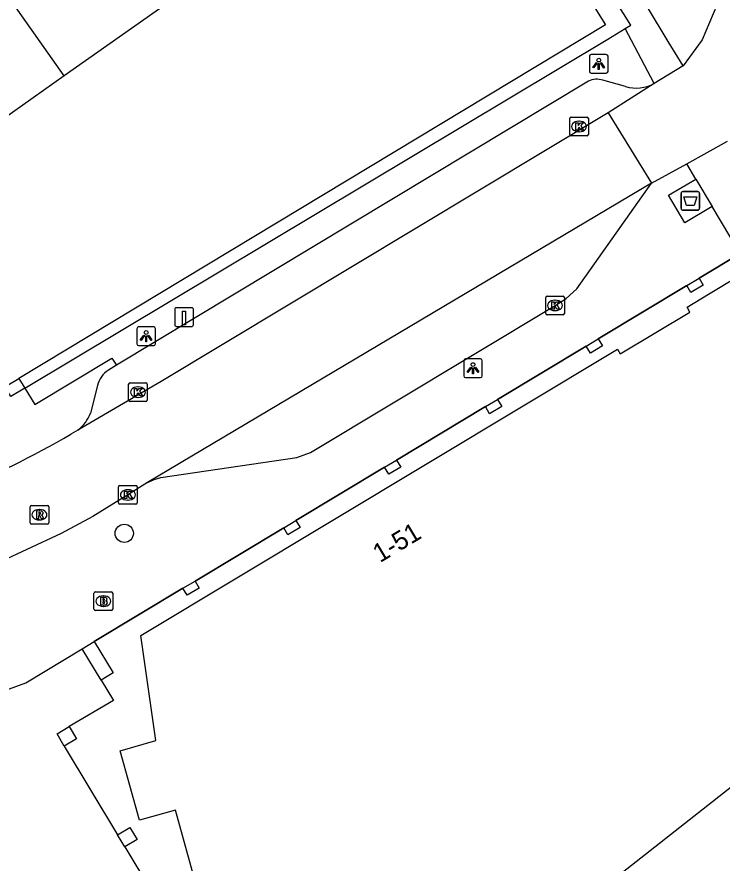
# Model space of a CAD drawing. Extents: x 159888 to 160757, y 384031 to 384746.
# Drawn here: x 160429.51 to 160467.29, y 384536.72 to 384582.04 of the extents above; entities that cross this region are included whole.
import ezdxf

# ---------------------------------------------------------------- set-up
doc = ezdxf.new("R2010")
doc.units = 0
for name, color, linetype in [('IMGEO_Afval_apart_plaats', 7, 'Continuous'), ('IMGEO_Boom', 7, 'Continuous'), ('IMGEO_Brandkraan', 7, 'Continuous'), ('IMGEO_Fietspad_gesloten', 7, 'Continuous'), ('IMGEO_Kolk', 7, 'Continuous'), ('IMGEO_Laadpaal', 7, 'Continuous'), ('IMGEO_Lichtpunt', 7, 'Continuous'), ('IMGEO_Pand', 7, 'Continuous'), ('IMGEO_Pand_nummerreeks', 7, 'Continuous'), ('IMGEO_Pand_overbouw', 7, 'Continuous'), ('IMGEO_Rijbaan_lokaal_gesloten', 7, 'Continuous'), ('IMGEO_Rijbaan_lokaal_open', 7, 'Continuous'), ('IMGEO_Rioolput', 7, 'Continuous'), ('IMGEO_Voetpad_gesloten', 7, 'Continuous'), ('IMGEO_Voetpad_open', 7, 'Continuous')]:
    doc.layers.add(name, color=color, linetype=linetype)

msp = doc.modelspace()

# ---------------------------------------------------------------- linework, layer by layer
at = {"layer": 'IMGEO_Afval_apart_plaats'}
for p, q in [((160465.088, 384571.791), (160465.088, 384572.591)), ((160465.088, 384572.591), (160465.088, 384571.791)), ((160465.188, 384572.691), (160465.978, 384572.691)), ((160465.978, 384572.691), (160465.188, 384572.691)), ((160466.078, 384572.591), (160466.078, 384571.791)), ((160466.078, 384571.791), (160466.078, 384572.591)), ((160465.978, 384571.691), (160465.188, 384571.691)), ((160465.188, 384571.691), (160465.978, 384571.691))]:
    msp.add_line(p, q, dxfattribs=at)
msp.add_lwpolyline([(160465.231, 384572.405), (160465.935, 384572.405), (160465.786, 384571.935), (160465.38, 384571.935), (160465.231, 384572.405)], dxfattribs=at)
for centre, start, end in [((160465.188, 384572.591), 90, 180), ((160465.188, 384572.591), 90, 180), ((160465.978, 384572.591), 0, 90), ((160465.978, 384572.591), 360, 90), ((160465.188, 384571.791), 180, 270), ((160465.188, 384571.791), 180, 270), ((160465.978, 384571.791), 270, 0), ((160465.978, 384571.791), 270, 0)]:
    msp.add_arc(centre, 0.1, start, end, dxfattribs=at)
at = {"layer": 'IMGEO_Boom'}
msp.add_circle((160435.258, 384554.38), 0.489, dxfattribs=at)
at = {"layer": 'IMGEO_Brandkraan'}
for p, q in [((160433.637, 384550.323), (160433.637, 384551.175)), ((160433.712, 384551.249), (160434.564, 384551.249)), ((160434.125, 384551.029), (160434.15, 384551.029)), ((160434.638, 384551.175), (160434.638, 384550.323)), ((160434.564, 384550.249), (160433.712, 384550.249)), ((160434.148, 384550.469), (160434.123, 384550.469))]:
    msp.add_line(p, q, dxfattribs=at)
for points in [[(160433.637, 384550.323), (160433.637, 384551.175)], [(160433.712, 384551.249), (160434.564, 384551.249)], [(160434.638, 384551.175), (160434.638, 384550.323)], [(160433.985, 384550.949), (160433.985, 384550.549), (160434.198, 384550.549)], [(160434.216, 384550.949), (160433.985, 384550.949)], [(160434.164, 384550.868), (160434.11, 384550.868), (160434.11, 384550.792)], [(160434.11, 384550.792), (160434.163, 384550.792)], [(160434.172, 384550.716), (160434.11, 384550.716), (160434.11, 384550.635)], [(160434.11, 384550.635), (160434.172, 384550.635)], [(160434.564, 384550.249), (160433.712, 384550.249)]]:
    msp.add_lwpolyline(points, dxfattribs=at)
for centre, radius, start, end in [((160433.714, 384551.173), 0.0765, 91.552, 178.448), ((160433.714, 384551.173), 0.0765, 91.552, 178.448), ((160434.562, 384551.173), 0.0765, 1.552, 88.448), ((160434.562, 384551.173), 0.0765, 1.552, 88.448), ((160434.165, 384550.83), 0.0379, 267.8285, 90.9355), ((160434.173, 384550.675), 0.0404, 269.8759, 90.5077), ((160434.204, 384550.8), 0.251, 268.6676, 293.5347), ((160434.22, 384550.804), 0.145, 59.4692, 91.5367), ((160434.245, 384550.851), 0.0922, 285.5137, 58.1501), ((160434.25, 384550.659), 0.105, 301.3115, 78.989), ((160433.714, 384550.325), 0.0765, 181.552, 268.448), ((160433.714, 384550.325), 0.0765, 181.552, 268.448), ((160434.562, 384550.325), 0.0765, 271.552, 358.448), ((160434.562, 384550.325), 0.0765, 271.552, 358.448)]:
    msp.add_arc(centre, radius, start, end, dxfattribs=at)
for centre, major_axis, ratio, start_param, end_param in [((160434.124, 384550.749), (-0.387, 0.002), 0.722429, 4.712389, 7.853982), ((160434.149, 384550.749), (-0.39, 0.002), 0.717154, 1.570796, 4.712389)]:
    msp.add_ellipse(centre, major_axis=major_axis, ratio=ratio, start_param=start_param, end_param=end_param, dxfattribs=at)
at = {"layer": 'IMGEO_Fietspad_gesloten'}
msp.add_lwpolyline([(160465.195, 384579.421), (160464.393, 384580.732), (160446.684, 384610.177)], dxfattribs=at)
at = {"layer": 'IMGEO_Kolk'}
for p, q in [((160459.123, 384575.749), (160459.123, 384576.601)), ((160459.198, 384576.675), (160460.05, 384576.675)), ((160459.611, 384576.455), (160459.636, 384576.455)), ((160460.124, 384576.601), (160460.124, 384575.749)), ((160459.634, 384575.895), (160459.609, 384575.895)), ((160460.05, 384575.675), (160459.198, 384575.675)), ((160457.837, 384566.163), (160457.837, 384567.015)), ((160457.912, 384567.089), (160458.764, 384567.089)), ((160458.325, 384566.869), (160458.35, 384566.869)), ((160458.838, 384567.015), (160458.838, 384566.163)), ((160458.764, 384566.089), (160457.912, 384566.089)), ((160458.348, 384566.309), (160458.323, 384566.309)), ((160435.491, 384561.517), (160435.491, 384562.369)), ((160435.566, 384562.443), (160436.418, 384562.443)), ((160436.492, 384562.369), (160436.492, 384561.517)), ((160435.979, 384562.223), (160436.004, 384562.223)), ((160436.418, 384561.443), (160435.566, 384561.443)), ((160436.002, 384561.663), (160435.977, 384561.663)), ((160434.951, 384556.014), (160434.951, 384556.866)), ((160435.026, 384556.94), (160435.878, 384556.94)), ((160435.952, 384556.866), (160435.952, 384556.014)), ((160435.439, 384556.72), (160435.464, 384556.72)), ((160435.462, 384556.16), (160435.437, 384556.16)), ((160435.878, 384555.94), (160435.026, 384555.94))]:
    msp.add_line(p, q, dxfattribs=at)
for points in [[(160459.123, 384575.749), (160459.123, 384576.601)], [(160459.198, 384576.675), (160460.05, 384576.675)], [(160459.444, 384576.375), (160459.567, 384576.375), (160459.567, 384576.224), (160459.697, 384576.375), (160459.861, 384576.375), (160459.715, 384576.224), (160459.868, 384575.975), (160459.716, 384575.975), (160459.631, 384576.139), (160459.567, 384576.072), (160459.567, 384575.975), (160459.444, 384575.975), (160459.444, 384576.375)], [(160460.124, 384576.601), (160460.124, 384575.749)], [(160460.05, 384575.675), (160459.198, 384575.675)], [(160457.837, 384566.163), (160457.837, 384567.015)], [(160457.912, 384567.089), (160458.764, 384567.089)], [(160458.838, 384567.015), (160458.838, 384566.163)], [(160458.158, 384566.789), (160458.281, 384566.789), (160458.281, 384566.638), (160458.411, 384566.789), (160458.575, 384566.789), (160458.429, 384566.638), (160458.582, 384566.389), (160458.43, 384566.389), (160458.345, 384566.553), (160458.281, 384566.486), (160458.281, 384566.389), (160458.158, 384566.389), (160458.158, 384566.789)], [(160458.764, 384566.089), (160457.912, 384566.089)], [(160435.491, 384561.517), (160435.491, 384562.369)], [(160435.566, 384562.443), (160436.418, 384562.443)], [(160436.492, 384562.369), (160436.492, 384561.517)], [(160435.812, 384562.143), (160435.935, 384562.143), (160435.935, 384561.992), (160436.065, 384562.143), (160436.229, 384562.143), (160436.083, 384561.992), (160436.236, 384561.743), (160436.084, 384561.743), (160435.999, 384561.907), (160435.935, 384561.84), (160435.935, 384561.743), (160435.812, 384561.743), (160435.812, 384562.143)], [(160436.418, 384561.443), (160435.566, 384561.443)], [(160434.951, 384556.014), (160434.951, 384556.866)], [(160435.026, 384556.94), (160435.878, 384556.94)], [(160435.952, 384556.866), (160435.952, 384556.014)], [(160435.272, 384556.64), (160435.395, 384556.64), (160435.395, 384556.489), (160435.525, 384556.64), (160435.689, 384556.64), (160435.543, 384556.489), (160435.696, 384556.24), (160435.544, 384556.24), (160435.459, 384556.404), (160435.395, 384556.337), (160435.395, 384556.24), (160435.272, 384556.24), (160435.272, 384556.64)], [(160435.878, 384555.94), (160435.026, 384555.94)]]:
    msp.add_lwpolyline(points, dxfattribs=at)
for centre, start, end in [((160459.2, 384576.599), 91.552, 178.448), ((160459.2, 384576.599), 91.552, 178.448), ((160460.048, 384576.599), 1.552, 88.448), ((160460.048, 384576.599), 1.552, 88.448), ((160459.2, 384575.751), 181.552, 268.448), ((160459.2, 384575.751), 181.552, 268.448), ((160460.048, 384575.751), 271.552, 358.448), ((160460.048, 384575.751), 271.552, 358.448), ((160457.914, 384567.013), 91.552, 178.448), ((160457.914, 384567.013), 91.552, 178.448), ((160458.762, 384567.013), 1.552, 88.448), ((160458.762, 384567.013), 1.552, 88.448), ((160457.914, 384566.165), 181.552, 268.448), ((160457.914, 384566.165), 181.552, 268.448), ((160458.762, 384566.165), 271.552, 358.448), ((160458.762, 384566.165), 271.552, 358.448), ((160435.568, 384562.367), 91.552, 178.448), ((160435.568, 384562.367), 91.552, 178.448), ((160436.416, 384562.367), 1.552, 88.448), ((160436.416, 384562.367), 1.552, 88.448), ((160435.568, 384561.519), 181.552, 268.448), ((160435.568, 384561.519), 181.552, 268.448), ((160436.416, 384561.519), 271.552, 358.448), ((160436.416, 384561.519), 271.552, 358.448), ((160435.028, 384556.864), 91.552, 178.448), ((160435.028, 384556.864), 91.552, 178.448), ((160435.876, 384556.864), 1.552, 88.448), ((160435.876, 384556.864), 1.552, 88.448), ((160435.028, 384556.016), 181.552, 268.448), ((160435.028, 384556.016), 181.552, 268.448), ((160435.876, 384556.016), 271.552, 358.448), ((160435.876, 384556.016), 271.552, 358.448)]:
    msp.add_arc(centre, 0.0765, start, end, dxfattribs=at)
for centre, major_axis, ratio, start_param, end_param in [((160459.61, 384576.175), (-0.387, 0.002), 0.722429, 4.712389, 7.853982), ((160459.635, 384576.175), (-0.39, 0.002), 0.717154, 1.570796, 4.712389), ((160458.324, 384566.589), (-0.387, 0.002), 0.722429, 4.712389, 7.853982), ((160458.349, 384566.589), (-0.39, 0.002), 0.717154, 1.570796, 4.712389), ((160435.978, 384561.943), (-0.387, 0.002), 0.722429, 4.712389, 7.853982), ((160436.003, 384561.943), (-0.39, 0.002), 0.717154, 1.570796, 4.712389), ((160435.438, 384556.44), (-0.387, 0.002), 0.722429, 4.712389, 7.853982), ((160435.463, 384556.44), (-0.39, 0.002), 0.717154, 1.570796, 4.712389)]:
    msp.add_ellipse(centre, major_axis=major_axis, ratio=ratio, start_param=start_param, end_param=end_param, dxfattribs=at)
at = {"layer": 'IMGEO_Laadpaal'}
for p, q in [((160437.963, 384566.384), (160437.963, 384565.543)), ((160437.963, 384566.384), (160437.963, 384565.543)), ((160438.879, 384566.468), (160438.038, 384566.468)), ((160438.879, 384566.468), (160438.038, 384566.468)), ((160438.963, 384565.552), (160438.963, 384566.393)), ((160438.963, 384565.552), (160438.963, 384566.393)), ((160438.047, 384565.468), (160438.888, 384565.468)), ((160438.047, 384565.468), (160438.888, 384565.468))]:
    msp.add_line(p, q, dxfattribs=at)
msp.add_lwpolyline([(160438.378, 384566.281), (160438.538, 384566.281), (160438.538, 384565.548), (160438.378, 384565.548), (160438.378, 384566.281)], dxfattribs=at)
for centre, start, end in [((160438.041, 384566.39), 92.4484, 184.2845), ((160438.041, 384566.39), 92.4484, 184.2845), ((160438.885, 384566.39), 2.4484, 94.2845), ((160438.885, 384566.39), 2.4484, 94.2845), ((160438.041, 384565.546), 182.4484, 274.2845), ((160438.041, 384565.546), 182.4484, 274.2845), ((160438.885, 384565.546), 272.4484, 4.2845), ((160438.885, 384565.546), 272.4484, 4.2845)]:
    msp.add_arc(centre, 0.0779, start, end, dxfattribs=at)
at = {"layer": 'IMGEO_Lichtpunt'}
for p, q in [((160461.082, 384580.029), (160460.274, 384580.029)), ((160461.082, 384580.029), (160460.274, 384580.029)), ((160460.18, 384579.934), (160460.18, 384579.127)), ((160460.18, 384579.934), (160460.18, 384579.127)), ((160461.176, 384579.127), (160461.176, 384579.934)), ((160461.176, 384579.127), (160461.176, 384579.934)), ((160460.274, 384579.033), (160461.082, 384579.033)), ((160460.274, 384579.033), (160461.082, 384579.033)), ((160435.932, 384565.341), (160435.932, 384564.534)), ((160435.932, 384565.341), (160435.932, 384564.534)), ((160436.834, 384565.436), (160436.026, 384565.436)), ((160436.834, 384565.436), (160436.026, 384565.436)), ((160436.928, 384564.534), (160436.928, 384565.341)), ((160436.928, 384564.534), (160436.928, 384565.341)), ((160436.026, 384564.44), (160436.834, 384564.44)), ((160436.026, 384564.44), (160436.834, 384564.44)), ((160454.345, 384563.72), (160453.537, 384563.72)), ((160454.345, 384563.72), (160453.537, 384563.72)), ((160453.443, 384563.625), (160453.443, 384562.818)), ((160453.443, 384563.625), (160453.443, 384562.818)), ((160454.439, 384562.818), (160454.439, 384563.625)), ((160454.439, 384562.818), (160454.439, 384563.625)), ((160453.537, 384562.724), (160454.345, 384562.724)), ((160453.537, 384562.724), (160454.345, 384562.724))]:
    msp.add_line(p, q, dxfattribs=at)
for points in [[(160460.554, 384579.598), (160460.593, 384579.57), (160460.405, 384579.308), (160460.367, 384579.335), (160460.554, 384579.598)], [(160460.656, 384579.55), (160460.703, 384579.55), (160460.703, 384579.228), (160460.656, 384579.228), (160460.656, 384579.55)], [(160460.766, 384579.57), (160460.804, 384579.597), (160460.991, 384579.335), (160460.952, 384579.307), (160460.766, 384579.57)], [(160436.306, 384565.005), (160436.345, 384564.977), (160436.157, 384564.715), (160436.119, 384564.742), (160436.306, 384565.005)], [(160436.408, 384564.957), (160436.455, 384564.957), (160436.455, 384564.635), (160436.408, 384564.635), (160436.408, 384564.957)], [(160436.518, 384564.977), (160436.556, 384565.004), (160436.743, 384564.742), (160436.704, 384564.714), (160436.518, 384564.977)], [(160453.817, 384563.289), (160453.856, 384563.261), (160453.668, 384562.999), (160453.63, 384563.026), (160453.817, 384563.289)], [(160453.919, 384563.241), (160453.966, 384563.241), (160453.966, 384562.919), (160453.919, 384562.919), (160453.919, 384563.241)], [(160454.029, 384563.261), (160454.067, 384563.288), (160454.254, 384563.026), (160454.215, 384562.998), (160454.029, 384563.261)]]:
    msp.add_lwpolyline(points, dxfattribs=at)
for centre in [(160460.679, 384579.732), (160436.431, 384565.139), (160453.942, 384563.423)]:
    msp.add_circle(centre, 0.0994, dxfattribs=at)
for centre, start, end in [((160460.274, 384579.934), 90, 180), ((160460.274, 384579.934), 90, 180), ((160461.082, 384579.934), 0, 90), ((160461.082, 384579.934), 0, 90), ((160460.274, 384579.127), 180, 270), ((160460.274, 384579.127), 180, 270), ((160461.082, 384579.127), 270, 0), ((160461.082, 384579.127), 270, 360), ((160436.026, 384565.341), 90, 180), ((160436.026, 384565.341), 90, 180), ((160436.834, 384565.341), 0, 90), ((160436.834, 384565.341), 0, 90), ((160436.026, 384564.534), 180, 270), ((160436.026, 384564.534), 180, 270), ((160436.834, 384564.534), 270, 0), ((160436.834, 384564.534), 270, 360), ((160453.537, 384563.625), 90, 180), ((160453.537, 384563.625), 90, 180), ((160454.345, 384563.625), 0, 90), ((160454.345, 384563.625), 0, 90), ((160453.537, 384562.818), 180, 270), ((160453.537, 384562.818), 180, 270), ((160454.345, 384562.818), 270, 0), ((160454.345, 384562.818), 270, 360)]:
    msp.add_arc(centre, 0.0946, start, end, dxfattribs=at)
at = {"layer": 'IMGEO_Pand'}
for points in [[(160453.478, 384593.674), (160461.033, 384581.623), (160429.614, 384562.681)], [(160432.047, 384578.89), (160429.131, 384583.037), (160435.204, 384587.306), (160438.111, 384583.181)], [(160438.111, 384583.181), (160432.047, 384578.89)], [(160432.047, 384578.89), (160423.166, 384572.604), (160426.417, 384566.77), (160428.859, 384562.226)], [(160445.899, 384523.596), (160445.557, 384524.165), (160445.433, 384524.372), (160443.403, 384527.748), (160439.447, 384534.325), (160438.003, 384539.546), (160436.076, 384539.012), (160435.044, 384542.736), (160436.954, 384543.281), (160436.151, 384548.915), (160461.68, 384564.249), (160461.834, 384563.992), (160465.563, 384566.236), (160465.409, 384566.493), (160466.566, 384567.188), (160468.137, 384568.133), (160468.762, 384567.092), (160478.909, 384550.185)], [(160465.394, 384567.655), (160466.054, 384568.046)], [(160466.054, 384568.046), (160466.278, 384567.667), (160465.618, 384567.276), (160465.394, 384567.655)], [(160460.003, 384564.411), (160460.651, 384564.801)], [(160460.651, 384564.801), (160460.877, 384564.424), (160460.229, 384564.034), (160460.003, 384564.411)], [(160428.859, 384562.226), (160429.614, 384562.681)], [(160454.605, 384561.168), (160455.253, 384561.557)], [(160455.253, 384561.557), (160455.479, 384561.18), (160454.832, 384560.791), (160454.605, 384561.168)], [(160449.201, 384557.92), (160449.85, 384558.308)], [(160449.85, 384558.308), (160450.076, 384557.93), (160449.426, 384557.542), (160449.201, 384557.92)], [(160443.8, 384554.678), (160444.449, 384555.066)], [(160444.449, 384555.066), (160444.675, 384554.688), (160444.026, 384554.3), (160443.8, 384554.678)], [(160438.4, 384551.441), (160439.051, 384551.824)], [(160439.051, 384551.824), (160439.274, 384551.445), (160438.623, 384551.062), (160438.4, 384551.441)], [(160479.161, 384549.765), (160471.203, 384543.477), (160445.899, 384523.596)], [(160433.002, 384548.194), (160433.645, 384548.583)], [(160433.645, 384548.583), (160434.663, 384546.901), (160434.02, 384546.512), (160433.002, 384548.194)], [(160431.658, 384543.639), (160432.312, 384544.026), (160432.7, 384543.369), (160432.045, 384542.983), (160431.658, 384543.639)], [(160434.9, 384538.236), (160435.551, 384538.628), (160435.942, 384537.979), (160435.29, 384537.588), (160434.9, 384538.236)]]:
    msp.add_lwpolyline(points, dxfattribs=at)
at = {"layer": 'IMGEO_Pand_overbouw'}
for points in [[(160468.257, 384569.373), (160466.054, 384568.046), (160466.278, 384567.667), (160465.618, 384567.276), (160465.394, 384567.655), (160460.651, 384564.801), (160460.877, 384564.424), (160460.229, 384564.034), (160460.003, 384564.411), (160455.253, 384561.557), (160455.479, 384561.18), (160454.832, 384560.791), (160454.605, 384561.168), (160449.85, 384558.308), (160450.076, 384557.93), (160449.426, 384557.542), (160449.201, 384557.92), (160444.449, 384555.066), (160444.675, 384554.688), (160444.026, 384554.3), (160443.8, 384554.678), (160439.051, 384551.824), (160439.274, 384551.445), (160438.623, 384551.062), (160438.4, 384551.441), (160433.645, 384548.583), (160434.663, 384546.901), (160434.02, 384546.512), (160434.677, 384545.426), (160432.312, 384544.026), (160432.7, 384543.369), (160432.045, 384542.983), (160434.9, 384538.236), (160435.551, 384538.628), (160435.942, 384537.979), (160435.29, 384537.588), (160438.144, 384532.838)], [(160439.447, 384534.325), (160438.003, 384539.546), (160436.076, 384539.012), (160435.044, 384542.736), (160436.954, 384543.281), (160436.151, 384548.915), (160461.68, 384564.249), (160461.834, 384563.992), (160465.563, 384566.236), (160465.409, 384566.493), (160466.566, 384567.188), (160468.137, 384568.133)]]:
    msp.add_lwpolyline(points, dxfattribs=at)
at = {"layer": 'IMGEO_Rijbaan_lokaal_gesloten'}
for points in [[(160467.002, 384582.668), (160466.21, 384580.825), (160465.195, 384579.421)], [(160465.195, 384579.421), (160463.642, 384578.473)], [(160463.642, 384578.473), (160461.191, 384576.901)], [(160461.191, 384576.901), (160463.506, 384573.139)], [(160465.391, 384574.168), (160467.569, 384575.383)], [(160463.506, 384573.139), (160465.391, 384574.168)]]:
    msp.add_lwpolyline(points, dxfattribs=at)
at = {"layer": 'IMGEO_Rijbaan_lokaal_open'}
for points in [[(160461.191, 384576.901), (160437.228, 384562.516), (160432.767, 384559.91)], [(160463.506, 384573.139), (160436.506, 384557.107)], [(160432.767, 384559.91), (160432.39, 384559.689)], [(160436.506, 384557.107), (160435.452, 384556.441), (160433.566, 384555.285), (160431.872, 384554.363), (160428.176, 384552.657), (160425.402, 384551.486)]]:
    msp.add_lwpolyline(points, dxfattribs=at)
msp.add_arc((160405.714, 384605.651), 53.143, 292.534, 300.1303, dxfattribs=at)
at = {"layer": 'IMGEO_Rioolput'}
for p, q in [((160430.215, 384554.952), (160430.215, 384555.804)), ((160430.29, 384555.878), (160431.142, 384555.878)), ((160430.703, 384555.658), (160430.728, 384555.658)), ((160431.216, 384555.804), (160431.216, 384554.952)), ((160430.726, 384555.098), (160430.701, 384555.098)), ((160431.142, 384554.878), (160430.29, 384554.878))]:
    msp.add_line(p, q, dxfattribs=at)
for points in [[(160430.215, 384554.952), (160430.215, 384555.804)], [(160430.29, 384555.878), (160431.142, 384555.878)], [(160430.804, 384555.576), (160430.552, 384555.578), (160430.552, 384555.178)], [(160430.73, 384555.497), (160430.676, 384555.497), (160430.676, 384555.416)], [(160431.216, 384555.804), (160431.216, 384554.952)], [(160430.552, 384555.178), (160430.676, 384555.178), (160430.676, 384555.34), (160430.687, 384555.34)], [(160430.676, 384555.416), (160430.728, 384555.416)], [(160430.734, 384555.311), (160430.805, 384555.178), (160430.945, 384555.178), (160430.88, 384555.304)], [(160431.142, 384554.878), (160430.29, 384554.878)]]:
    msp.add_lwpolyline(points, dxfattribs=at)
for centre, radius, start, end in [((160430.292, 384555.802), 0.0765, 91.552, 178.448), ((160430.292, 384555.802), 0.0765, 91.552, 178.448), ((160430.736, 384555.401), 0.0964, 77.0061, 93.1865), ((160430.75, 384555.458), 0.0378, 276.6634, 79.6772), ((160430.803, 384555.466), 0.109, 350.3612, 89.416), ((160431.14, 384555.802), 0.0765, 1.552, 88.448), ((160431.14, 384555.802), 0.0765, 1.552, 88.448), ((160430.686, 384555.287), 0.0533, 26.0293, 88.6989), ((160430.712, 384555.605), 0.19, 274.7715, 282.9687), ((160430.801, 384555.466), 0.112, 277.5842, 350.9817), ((160430.785, 384555.251), 0.108, 29.5134, 73.7905), ((160430.292, 384554.954), 0.0765, 181.552, 268.448), ((160430.292, 384554.954), 0.0765, 181.552, 268.448), ((160431.14, 384554.954), 0.0765, 271.552, 358.448), ((160431.14, 384554.954), 0.0765, 271.552, 358.448)]:
    msp.add_arc(centre, radius, start, end, dxfattribs=at)
for centre, major_axis, ratio, start_param, end_param in [((160430.702, 384555.378), (-0.387, 0.002), 0.722429, 4.712389, 7.853982), ((160430.727, 384555.378), (-0.39, 0.002), 0.717154, 1.570796, 4.712389)]:
    msp.add_ellipse(centre, major_axis=major_axis, ratio=ratio, start_param=start_param, end_param=end_param, dxfattribs=at)
at = {"layer": 'IMGEO_Voetpad_gesloten'}
for points in [[(160466.748, 384571.889), (160465.295, 384571.022), (160464.418, 384572.493), (160465.871, 384573.36)], [(160465.871, 384573.36), (160466.748, 384571.889)]]:
    msp.add_lwpolyline(points, dxfattribs=at)
at = {"layer": 'IMGEO_Voetpad_open'}
for points in [[(160462.088, 384581.42), (160462.394, 384581.605), (160458.462, 384587.864), (160454.434, 384594.24), (160453.478, 384593.674)], [(160429.927, 384562.164), (160461.157, 384580.856), (160462.088, 384581.42)], [(160463.642, 384578.473), (160462.088, 384581.42)], [(160460.123, 384578.61), (160434.834, 384563.381)], [(160462.118, 384578.314), (160460.898, 384578.651)], [(160465.871, 384573.36), (160465.391, 384574.168)], [(160436.506, 384557.107), (160436.857, 384557.271), (160437.223, 384557.371), (160444.495, 384558.444), (160445.235, 384558.712), (160458.337, 384566.59), (160458.925, 384566.958), (160459.498, 384567.481), (160463.506, 384573.139)], [(160468.257, 384569.373), (160466.748, 384571.889)], [(160466.054, 384568.046), (160468.257, 384569.373)], [(160460.651, 384564.801), (160465.394, 384567.655)], [(160455.253, 384561.557), (160460.003, 384564.411)], [(160429.927, 384562.164), (160430.463, 384561.279), (160434.587, 384563.77), (160434.834, 384563.381)], [(160434.834, 384563.381), (160434.412, 384563.116)], [(160429.614, 384562.681), (160429.927, 384562.164)], [(160433.831, 384562.3), (160433.45, 384560.821)], [(160429.927, 384562.164), (160429.173, 384561.715), (160428.859, 384562.226)], [(160449.85, 384558.308), (160454.605, 384561.168)], [(160444.449, 384555.066), (160449.201, 384557.92)], [(160439.051, 384551.824), (160443.8, 384554.678)], [(160433.645, 384548.583), (160438.4, 384551.441)], [(160427.82, 384545.58), (160429.994, 384546.375), (160433.002, 384548.194)]]:
    msp.add_lwpolyline(points, dxfattribs=at)
for centre, radius, start, end in [((160460.565, 384577.601), 1.102, 72.4091, 113.6476), ((160462.685, 384580.26), 2.027, 253.7499, 298.1624), ((160435.018, 384562.069), 1.209, 120.0848, 169.0127), ((160431.581, 384561.511), 1.992, 306.5359, 339.7444)]:
    msp.add_arc(centre, radius, start, end, dxfattribs=at)

# ---------------------------------------------------------------- texts
at = {"layer": 'IMGEO_Pand_nummerreeks'}
msp.add_text('1-51', height=1, rotation=30.9913, dxfattribs=at).set_placement((160448.959, 384552.782))

doc.saveas('drawing.dxf')
